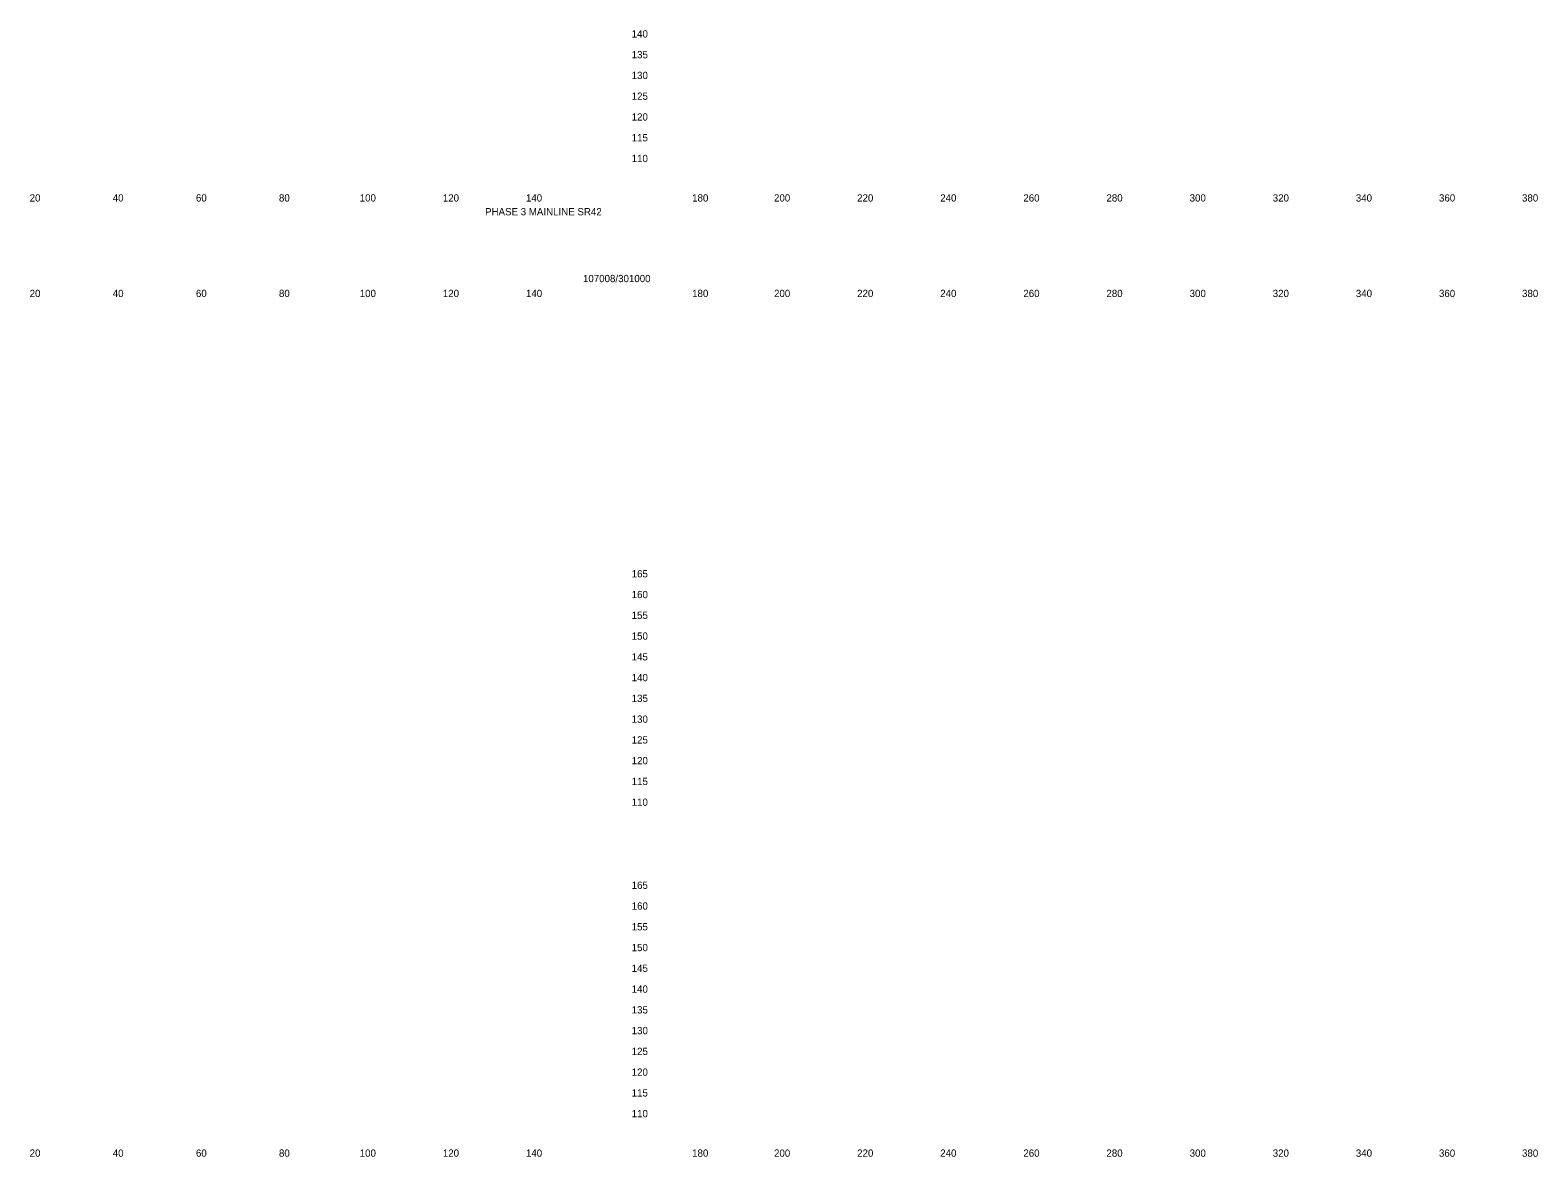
# Model space of a CAD drawing. Extents: x 21281 to 22024, y 6472 to 15198.
# Drawn here: x 21661.4 to 22024.2, y 9465.3 to 9736.6 of the extents above; entities that cross this region are included whole.
import ezdxf

# ---------------------------------------------------------------- set-up
doc = ezdxf.new("R2010")
doc.units = 0
doc.layers.add('Draft_XS_Grid', color=7, linetype='Continuous')
doc.layers.add('Draft_XS_Text', color=7, linetype='Continuous')

msp = doc.modelspace()

# ---------------------------------------------------------------- texts
at = {"layer": 'Draft_XS_Grid'}
for s, p in [('  140  ', (21804.84, 9734.84)), ('  135  ', (21804.84, 9729.84)), ('  130  ', (21804.84, 9724.84)), ('  125  ', (21804.84, 9719.84)), ('  120  ', (21804.84, 9714.84)), ('  115  ', (21804.84, 9709.84)), ('  110  ', (21804.84, 9704.84)), ('  165  ', (21804.84, 9604.84)), ('  160  ', (21804.84, 9599.84)), ('  155  ', (21804.84, 9594.84)), ('  150  ', (21804.84, 9589.84)), ('  145  ', (21804.84, 9584.84)), ('  140  ', (21804.84, 9579.84)), ('  135  ', (21804.84, 9574.84)), ('  130  ', (21804.84, 9569.84)), ('  125  ', (21804.84, 9564.84)), ('  120  ', (21804.84, 9559.84)), ('  115  ', (21804.84, 9554.84)), ('  110  ', (21804.84, 9549.84)), ('  165  ', (21804.84, 9529.84)), ('  160  ', (21804.84, 9524.84)), ('  155  ', (21804.84, 9519.84)), ('  150  ', (21804.84, 9514.84)), ('  145  ', (21804.84, 9509.84)), ('  140  ', (21804.84, 9504.84)), ('  135  ', (21804.84, 9499.84)), ('  130  ', (21804.84, 9494.84)), ('  125  ', (21804.84, 9489.84)), ('  120  ', (21804.84, 9484.84)), ('  115  ', (21804.84, 9479.84)), ('  110  ', (21804.84, 9474.84))]:
    msp.add_text(s, height=1.75, dxfattribs=at).set_placement(p)
at = {"layer": 'Draft_XS_Text'}
for s, p in [('  20  ', (21659.95, 9695.34)), ('  40  ', (21679.95, 9695.34)), ('  60  ', (21699.97, 9695.34)), ('  80  ', (21719.95, 9695.34)), ('  100  ', (21739.39, 9695.34)), ('  120  ', (21759.39, 9695.34)), ('  140  ', (21779.39, 9695.34)), ('  180  ', (21819.39, 9695.34)), ('  200  ', (21839.1, 9695.34)), ('  220  ', (21859.1, 9695.34)), ('  240  ', (21879.1, 9695.34)), ('  260  ', (21899.11, 9695.34)), ('  280  ', (21919.1, 9695.34)), ('  300  ', (21939.13, 9695.34)), ('  320  ', (21959.13, 9695.34)), ('  340  ', (21979.13, 9695.34)), ('  360  ', (21999.14, 9695.34)), ('  380  ', (22019.13, 9695.34)), ('PHASE 3 MAINLINE SR42', (21770.85, 9692.02)), ('107008/301000', (21794.42, 9675.93)), ('  20  ', (21659.95, 9672.34)), ('  40  ', (21679.95, 9672.34)), ('  60  ', (21699.97, 9672.34)), ('  80  ', (21719.95, 9672.34)), ('  100  ', (21739.39, 9672.34)), ('  120  ', (21759.39, 9672.34)), ('  140  ', (21779.39, 9672.34)), ('  180  ', (21819.39, 9672.34)), ('  200  ', (21839.1, 9672.34)), ('  220  ', (21859.1, 9672.34)), ('  240  ', (21879.1, 9672.34)), ('  260  ', (21899.11, 9672.34)), ('  280  ', (21919.1, 9672.34)), ('  300  ', (21939.13, 9672.34)), ('  320  ', (21959.13, 9672.34)), ('  340  ', (21979.13, 9672.34)), ('  360  ', (21999.14, 9672.34)), ('  380  ', (22019.13, 9672.34)), ('  20  ', (21659.95, 9465.34)), ('  40  ', (21679.95, 9465.34)), ('  60  ', (21699.97, 9465.34)), ('  80  ', (21719.95, 9465.34)), ('  100  ', (21739.39, 9465.34)), ('  120  ', (21759.39, 9465.34)), ('  140  ', (21779.39, 9465.34)), ('  180  ', (21819.39, 9465.34)), ('  200  ', (21839.1, 9465.34)), ('  220  ', (21859.1, 9465.34)), ('  240  ', (21879.1, 9465.34)), ('  260  ', (21899.11, 9465.34)), ('  280  ', (21919.1, 9465.34)), ('  300  ', (21939.13, 9465.34)), ('  320  ', (21959.13, 9465.34)), ('  340  ', (21979.13, 9465.34)), ('  360  ', (21999.14, 9465.34)), ('  380  ', (22019.13, 9465.34))]:
    msp.add_text(s, height=1.75, dxfattribs=at).set_placement(p)

doc.saveas('drawing.dxf')
